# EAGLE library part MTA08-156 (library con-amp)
AMP connector
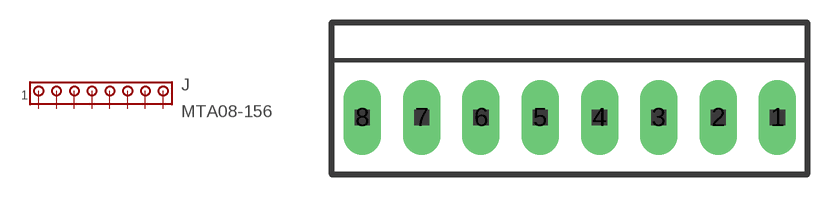
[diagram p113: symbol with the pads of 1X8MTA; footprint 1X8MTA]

Designator prefix J

## MTA08-156 (OC_FARNELL: unknown; OC_NEWARK: unknown)  [1X8MTA]
1  1  pas
2  2  pas
3  3  pas
4  4  pas
5  5  pas
6  6  pas
7  7  pas
8  8  pas

## Footprint 1X8MTA (pad centres in mm)
AMP MTA connector
drill 1.676 long: 1 13.868,0; 2 9.906,0; 3 5.944,0; 4 1.981,0; 5 -1.981,0; 6 -5.944,0; 7 -9.906,0; 8 -13.868,0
